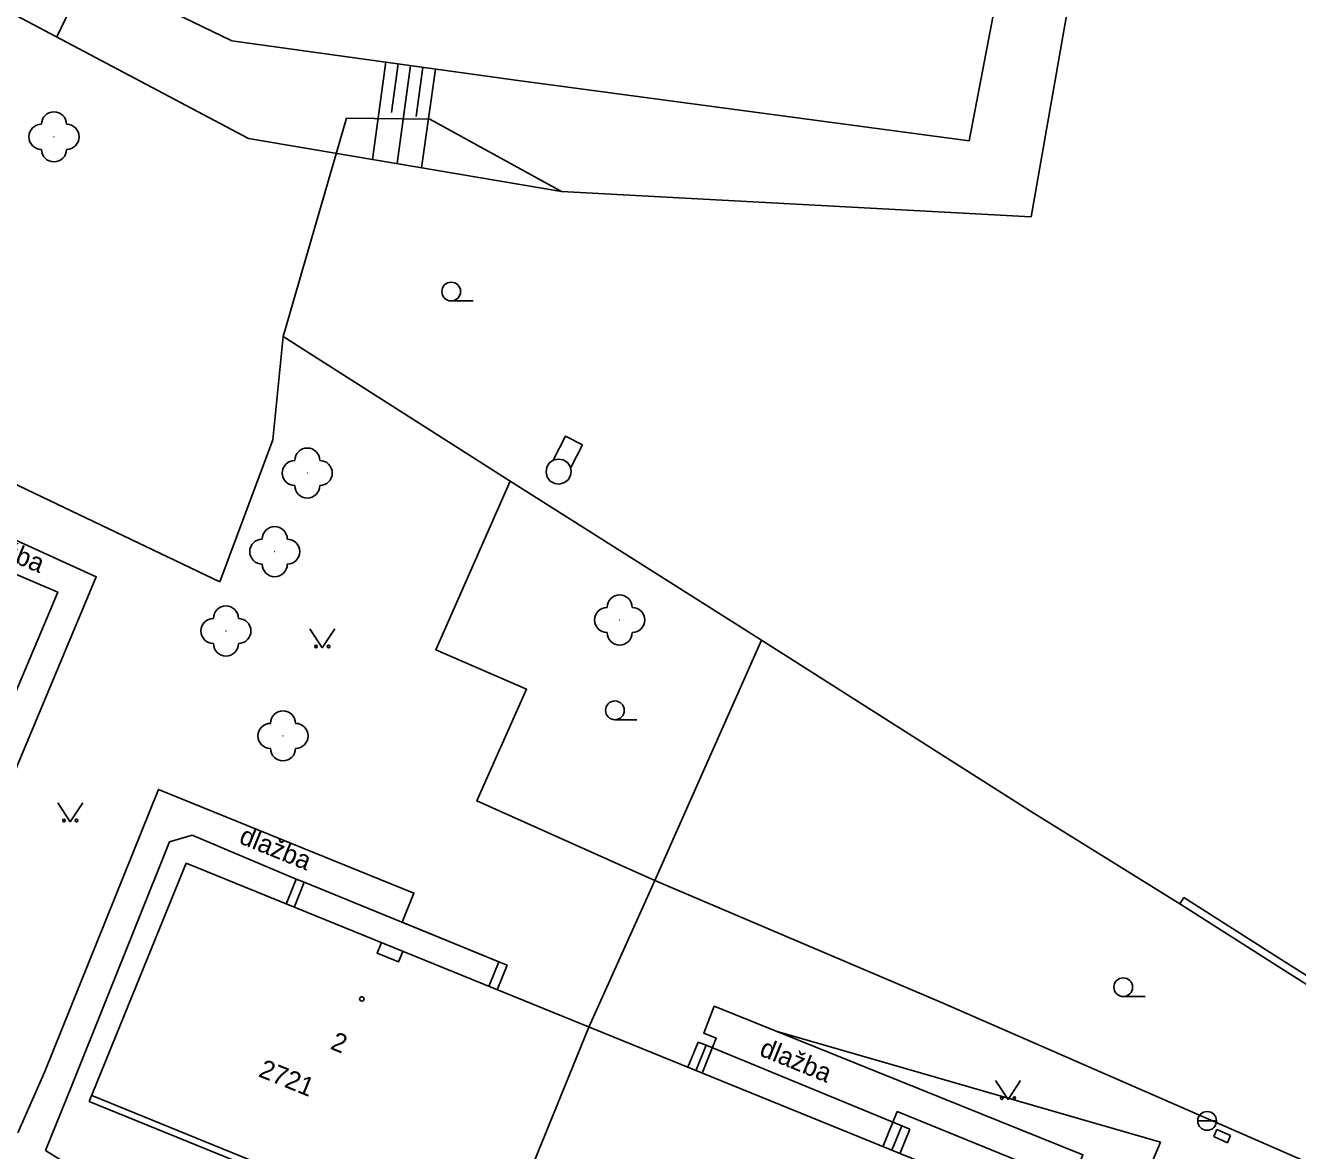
# Model space of a CAD drawing. Extents: x -584400 to -581602, y -1210894 to -1208793.
# Drawn here: x -582410.9 to -582360, y -1209985.8 to -1209940.8 of the extents above; entities that cross this region are included whole.
import ezdxf

# ---------------------------------------------------------------- set-up
doc = ezdxf.new("R2010")
doc.units = 0
for name, color, linetype in [('BUDOVY_MĚŘ', 7, 'Continuous'), ('POMOC_POPIS', 7, 'Continuous'), ('ROZHRANÍ_PLOCH', 7, 'Continuous'), ('VÝŠKOPIS', 7, 'Continuous'), ('ZELEŇ', 7, 'Continuous'), ('ZN_BUDOV', 7, 'Continuous'), ('ZN_DOPLŇKOVÉ', 7, 'Continuous'), ('ZN_KULTUR', 7, 'Continuous'), ('Č_POPIS_EVID', 7, 'Continuous')]:
    doc.layers.add(name, color=color, linetype=linetype)

msp = doc.modelspace()

# ---------------------------------------------------------------- linework, layer by layer
at = {"layer": 'BUDOVY_MĚŘ'}
for points in [[(-582408.32, -1209983.83), (-582404.45, -1209974.31)], [(-582404.45, -1209974.31), (-582371.97, -1209987.52)], [(-582400.45, -1209975.94), (-582400.05, -1209974.94)], [(-582400.05, -1209974.94), (-582399.73, -1209975.07)], [(-582399.73, -1209975.07), (-582400.13, -1209976.07)], [(-582399.73, -1209975.07), (-582391.96, -1209978.25)], [(-582396.65, -1209977.48), (-582396.82, -1209977.9), (-582395.96, -1209978.25), (-582395.79, -1209977.83)], [(-582391.96, -1209978.25), (-582392.36, -1209979.23)], [(-582391.63, -1209978.38), (-582392.03, -1209979.36)], [(-582391.96, -1209978.25), (-582391.63, -1209978.38)], [(-582392.14, -1209990.15), (-582388.36, -1209980.85)], [(-582384.4, -1209982.46), (-582383.99, -1209981.45)], [(-582383.67, -1209981.58), (-582384.08, -1209982.6)], [(-582383.99, -1209981.45), (-582383.67, -1209981.58)], [(-582383.67, -1209981.58), (-582375.86, -1209984.8)], [(-582375.88, -1209997.02), (-582408.32, -1209983.83)], [(-582375.86, -1209984.8), (-582376.26, -1209985.77)], [(-582375.54, -1209984.93), (-582375.94, -1209985.91)], [(-582375.86, -1209984.8), (-582375.54, -1209984.93)], [(-582363.39, -1209985.23), (-582363.27, -1209984.95)], [(-582363.27, -1209984.95), (-582362.72, -1209985.19)], [(-582362.84, -1209985.47), (-582362.72, -1209985.19)], [(-582363.39, -1209985.23), (-582362.84, -1209985.47)]]:
    msp.add_lwpolyline(points, dxfattribs=at)
at = {"layer": 'ROZHRANÍ_PLOCH'}
for points in [[(-582389.78, -1209958.2), (-582389.3, -1209957.25), (-582388.62, -1209957.59)], [(-582389.1, -1209958.53), (-582388.62, -1209957.59)], [(-582422.47, -1209958.07), (-582419.2, -1209959.48), (-582418.63, -1209958.05), (-582408.04, -1209962.86), (-582413.15, -1209975.04)], [(-582389.1, -1209958.53), (-582389.11, -1209958.46), (-582389.22, -1209958.3), (-582389.39, -1209958.19), (-582389.58, -1209958.16), (-582389.78, -1209958.2), (-582389.94, -1209958.32), (-582390.04, -1209958.49), (-582390.07, -1209958.69), (-582390.02, -1209958.88), (-582389.9, -1209959.04), (-582389.72, -1209959.14), (-582389.53, -1209959.16), (-582389.34, -1209959.1), (-582389.18, -1209958.98), (-582389.09, -1209958.8), (-582389.07, -1209958.66), (-582389.1, -1209958.53)], [(-582414.26, -1209974.57), (-582409.58, -1209963.48), (-582414.79, -1209961.25)], [(-582410.1, -1209982.63), (-582405.56, -1209971.36), (-582395.35, -1209975.5), (-582395.82, -1209976.66), (-582391.96, -1209978.25)], [(-582400.05, -1209974.94), (-582404.21, -1209973.19), (-582405.11, -1209973.45), (-582409.02, -1209983.18)], [(-582383.84, -1209982.69), (-582383.27, -1209981.29), (-582383.77, -1209981.1), (-582383.35, -1209980.02), (-582368.62, -1209985.95), (-582373.32, -1209997.65)], [(-582411.18, -1209985.08), (-582410.1, -1209982.63)], [(-582409.02, -1209983.18), (-582410.07, -1209985.78)], [(-582408.22, -1209983.59), (-582400.93, -1209986.56)], [(-582374.52, -1209997.17), (-582370.2, -1209986.61), (-582376.04, -1209984.23), (-582376.61, -1209985.63)], [(-582410.07, -1209985.78), (-582402.46, -1209990.5)]]:
    msp.add_lwpolyline(points, dxfattribs=at)
at = {"layer": 'VÝŠKOPIS'}
for points in [[(-582458.53, -1209884.77), (-582456.6, -1209886.04), (-582449.67, -1209886.53), (-582449.3, -1209900.15), (-582450.73, -1209918.74), (-582447.81, -1209922.68), (-582434.61, -1209928.59), (-582420.34, -1209935.62), (-582401.96, -1209945.35), (-582389.45, -1209947.48)], [(-582391.38, -1209943.01), (-582402.62, -1209941.45), (-582418.91, -1209933.59), (-582430.07, -1209926.24), (-582446.8, -1209919.9), (-582447.79, -1209918.59), (-582447.46, -1209900.26), (-582446.56, -1209884.67)], [(-582370.18, -1209929.86), (-582373.17, -1209945.45)], [(-582370.69, -1209948.48), (-582367.5, -1209930.35)], [(-582409.62, -1209941.3), (-582408.36, -1209938.68)], [(-582397.01, -1209946.19), (-582396.47, -1209942.3)], [(-582396.25, -1209944.32), (-582395.98, -1209942.37)], [(-582396.02, -1209946.36), (-582395.48, -1209942.44)], [(-582395.26, -1209944.48), (-582394.99, -1209942.51)], [(-582395.04, -1209946.53), (-582394.49, -1209942.58)], [(-582373.17, -1209945.45), (-582391.38, -1209943.01)], [(-582389.45, -1209947.48), (-582370.69, -1209948.48)], [(-582380.84, -1209981.03), (-582365.52, -1209985.45)], [(-582365.52, -1209985.45), (-582371.35, -1209999.3)]]:
    msp.add_lwpolyline(points, dxfattribs=at)
at = {"layer": 'ZELEŇ'}
for points in [[(-582436.72, -1209927.64), (-582442.95, -1209945.51), (-582431.5, -1209950.17), (-582420.63, -1209954.71), (-582403.11, -1209963.06), (-582400.98, -1209957.39), (-582400.57, -1209953.27)], [(-582391.51, -1209959.05), (-582394.48, -1209965.78), (-582390.85, -1209967.36), (-582392.84, -1209971.82), (-582385.72, -1209975), (-582374.18, -1209979.91), (-582355.73, -1209987.97), (-582352.6, -1209983.62)]]:
    msp.add_lwpolyline(points, dxfattribs=at)
for centre in [(-582409.73, -1209945.29), (-582399.61, -1209958.72), (-582400.91, -1209961.86), (-582387.13, -1209964.59), (-582402.86, -1209965.03), (-582400.58, -1209969.22)]:
    msp.add_circle(centre, 0.0005, dxfattribs=at)
for centre, start, end in [((-582409.73, -1209944.79), 0, 180), ((-582410.23, -1209945.29), 90, 270), ((-582409.23, -1209945.29), 270, 90), ((-582409.73, -1209945.79), 180, 360), ((-582399.61, -1209958.22), 0, 180), ((-582400.11, -1209958.72), 90, 270), ((-582399.11, -1209958.72), 270, 90), ((-582399.61, -1209959.22), 180, 360), ((-582400.91, -1209961.36), 0, 180), ((-582401.41, -1209961.86), 90, 270), ((-582400.41, -1209961.86), 270, 90), ((-582400.91, -1209962.36), 180, 360), ((-582387.13, -1209964.09), 0, 180), ((-582402.86, -1209964.53), 0, 180), ((-582387.63, -1209964.59), 90, 270), ((-582386.63, -1209964.59), 270, 90), ((-582403.36, -1209965.03), 90, 270), ((-582402.36, -1209965.03), 270, 90), ((-582387.13, -1209965.09), 180, 360), ((-582402.86, -1209965.53), 180, 360), ((-582400.58, -1209968.72), 0, 180), ((-582401.08, -1209969.22), 90, 270), ((-582400.08, -1209969.22), 270, 90), ((-582400.58, -1209969.72), 180, 360)]:
    msp.add_arc(centre, 0.5, start, end, dxfattribs=at)
at = {"layer": 'ZN_BUDOV'}
msp.add_circle((-582397.43, -1209979.73), 0.0875, dxfattribs=at)
at = {"layer": 'ZN_DOPLŇKOVÉ'}
msp.add_line((-582364.035, -1209984.6), (-582363.285, -1209984.6), dxfattribs=at)
for points in [[(-582389.45, -1209947.48), (-582394.71, -1209944.58), (-582398.04, -1209944.54), (-582400.57, -1209953.27), (-582391.51, -1209959.05), (-582381.46, -1209965.4), (-582370.72, -1209972.23), (-582364.75, -1209975.93)], [(-582381.46, -1209965.4), (-582385.72, -1209975), (-582388.36, -1209980.85)], [(-582349.71, -1209984.55), (-582349.83, -1209984.82), (-582352.6, -1209983.62), (-582360.72, -1209978.5), (-582364.75, -1209975.93), (-582364.59, -1209975.68)], [(-582364.59, -1209975.68), (-582360.56, -1209978.25), (-582352.46, -1209983.35), (-582349.71, -1209984.55)]]:
    msp.add_lwpolyline(points, dxfattribs=at)
msp.add_circle((-582363.66, -1209984.6), 0.375, dxfattribs=at)
at = {"layer": 'ZN_KULTUR'}
for p, q in [((-582393.86, -1209951.845), (-582392.985, -1209951.845)), ((-582387.32, -1209968.575), (-582386.445, -1209968.575)), ((-582367.01, -1209979.635), (-582366.135, -1209979.635))]:
    msp.add_line(p, q, dxfattribs=at)
for points in [[(-582399.51, -1209964.95), (-582399.01, -1209965.7), (-582398.51, -1209964.95)], [(-582409.58, -1209971.9), (-582409.08, -1209972.65), (-582408.58, -1209971.9)], [(-582372.11, -1209982.99), (-582371.61, -1209983.74), (-582371.11, -1209982.99)]]:
    msp.add_lwpolyline(points, dxfattribs=at)
for centre, radius in [((-582393.86, -1209951.47), 0.375), ((-582399.26, -1209965.65), 0.05), ((-582398.76, -1209965.65), 0.05), ((-582387.32, -1209968.2), 0.375), ((-582409.33, -1209972.6), 0.05), ((-582408.83, -1209972.6), 0.05), ((-582367.01, -1209979.26), 0.375), ((-582371.86, -1209983.69), 0.05), ((-582371.36, -1209983.69), 0.05)]:
    msp.add_circle(centre, radius, dxfattribs=at)

# ---------------------------------------------------------------- texts
at = {"layer": 'POMOC_POPIS'}
for p in [(-582413.04, -1209961.61), (-582402.38, -1209973.49), (-582381.59, -1209981.97)]:
    msp.add_text('dlažba', height=0.75, rotation=337.8678, dxfattribs=at).set_placement(p)
at = {"layer": 'Č_POPIS_EVID'}
for s, p in [('2', (-582398.73, -1209981.71)), ('2721', (-582401.6, -1209982.81))]:
    msp.add_text(s, height=0.75, rotation=337.883, dxfattribs=at).set_placement(p)

doc.saveas('drawing.dxf')
